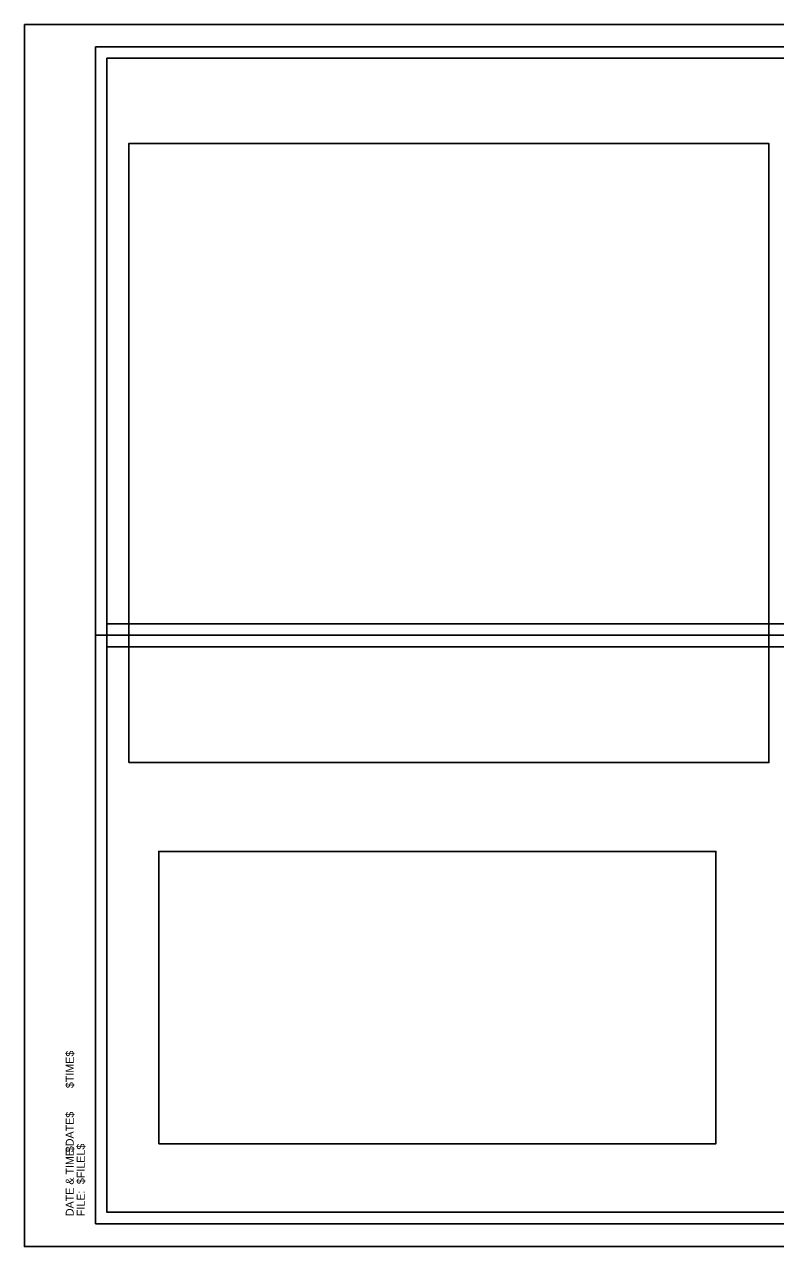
# Model space of a CAD drawing. Extents: x 1369655 to 1370989, y 380216 to 380430.
# Drawn here: x 1370155.2 to 1370286.3, y 380216.4 to 380429.8 of the extents above; entities that cross this region are included whole.
import ezdxf

# ---------------------------------------------------------------- set-up
doc = ezdxf.new("R2010")
doc.units = 0
for name, color, linetype in [('Default', 7, 'Continuous'), ('R_Border', 7, 'Continuous'), ('R_Border Notes', 7, 'Continuous'), ('R_Border Plan-Plan', 7, 'Continuous'), ('R_No Plot', 7, 'Continuous')]:
    doc.layers.add(name, color=color, linetype=linetype)

msp = doc.modelspace()

# ---------------------------------------------------------------- linework, layer by layer
at = {"layer": 'Default'}
for points in [[(1370173.46, 380300.91), (1370285.15, 380300.91), (1370285.15, 380408.95), (1370173.46, 380408.95)], [(1370178.69, 380234.37), (1370275.92, 380234.37), (1370275.92, 380285.41), (1370178.69, 380285.41)]]:
    msp.add_lwpolyline(points, close=True, dxfattribs=at)
at = {"layer": 'R_Border'}
for p, q in [((1370167.65, 380425.87), (1370483.83, 380425.87)), ((1370167.65, 380220.41), (1370167.65, 380425.87)), ((1370167.65, 380220.41), (1370167.65, 380220.41)), ((1370483.83, 380220.41), (1370167.65, 380220.41))]:
    msp.add_line(p, q, dxfattribs=at)
at = {"layer": 'R_Border Plan-Plan'}
msp.add_line((1370167.65, 380323.14), (1370483.83, 380323.14), dxfattribs=at)
at = {"layer": 'R_No Plot'}
for points in [[(1370155.25, 380429.76), (1370488.59, 380429.76), (1370488.59, 380216.42), (1370155.25, 380216.42)], [(1370481.83, 380325.14), (1370169.65, 380325.14), (1370169.65, 380423.87), (1370419.19, 380423.87), (1370419.19, 380413.99), (1370436.73, 380413.99), (1370460.83, 380413.99), (1370460.83, 380391.65), (1370481.83, 380391.65)], [(1370169.65, 380423.87), (1370419.19, 380423.87), (1370419.19, 380413.99), (1370436.73, 380413.99), (1370460.83, 380413.99), (1370460.83, 380391.65), (1370481.83, 380391.65), (1370481.83, 380222.41), (1370169.65, 380222.41)], [(1370169.65, 380321.14), (1370481.83, 380321.14), (1370481.83, 380222.41), (1370169.65, 380222.41)]]:
    msp.add_lwpolyline(points, close=True, dxfattribs=at)

# ---------------------------------------------------------------- texts
at = {"layer": 'R_Border Notes'}
for s, height, p in [('$TIME$', 1.397, (1370163.85, 380244.08)), ('$DATE$', 1.397, (1370163.85, 380232.9)), ('DATE & TIME:', 1.3968, (1370163.85, 380221.73)), ('$FILEL$', 1.397, (1370165.77, 380227.32)), ('FILE: ', 1.397, (1370165.77, 380221.73))]:
    msp.add_text(s, height=height, rotation=90, dxfattribs=at).set_placement(p)

doc.saveas('drawing.dxf')
